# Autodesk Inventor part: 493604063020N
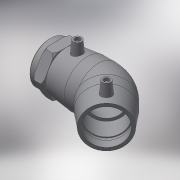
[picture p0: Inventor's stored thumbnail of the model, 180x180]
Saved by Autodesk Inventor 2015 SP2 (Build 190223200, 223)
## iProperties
Created: 2017-06
Part Number: 493604063020N
Material: Generic
Description: PLASSON 45° ELBOW TRANSITION FEMALE 63-2"
Document SubType Name: Modeling
Designer: KIM
Mass: 487.238 g
Surface Area: 998.178 cm^2
Volume: 487.238 cm^3
Density: 1 g/cm^3
Appearance: Default
Author: KIM
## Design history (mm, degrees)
derived "493604.ipt"
feature "Solid1::493604.ipt"
tag "TaggingFeature1"
body "Solid1"
other parameters: "d2" = 82, "d4" = 36.5, "d5" = 73.8, "d8" = 168 deg, "d10" = 23.2, "d11" = 7.73333, "d29" = 57, "d30" = 15, "d31" = 51.1, "d34" = 5 deg, "d41" = 4, "d42" = 14, "d43" = 0, "d49" = 63, "d50" = 53.55, "d51" = 23.2, "d52" = 58, "d54" = 135 deg, "d86" = 36.9, "d87" = 135 deg, "d88" = 146, "d90" = 58, "d91" = 0, "d92" = 58, "d93" = 0, "d101" = 3, "d102" = 0, "d107" = 0.1, "d108" = 49, "d110" = 62, "d112" = 73.8, "d113" = 56.656, "d114" = 55.8, "d128" = 37.2, "d129" = 0, "d132" = 3.15, "d133" = 45 deg, "d134" = 45 deg, "d136" = 1.89, "d_" = 63, "L_" = 208, "L_1" = 58, "D_" = 49, "A_" = 57, "d_2" = 12, "L_2" = 62, "Rp_" = 56.656, "D_1" = 82
